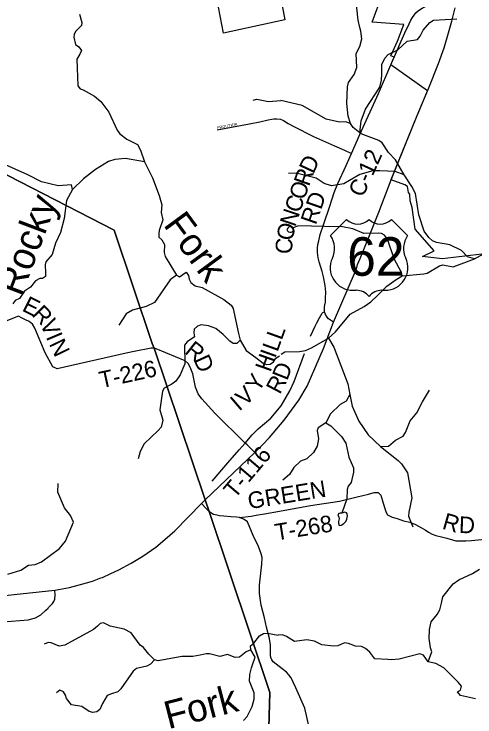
# Model space of a CAD drawing. Extents: x 1525783 to 1900577, y 218250 to 627376.
# Drawn here: x 1644767 to 1653092, y 423185 to 435875 of the extents above; entities that cross this region are included whole.
import ezdxf

# ---------------------------------------------------------------- set-up
doc = ezdxf.new("R2010")
doc.units = 0
for name, color, linetype in [('GM_X_City_Street', 7, 'Continuous'), ('GM_X_Corporation', 7, 'Continuous'), ('GM_X_County_Road', 7, 'Continuous'), ('GM_X_County_Road_Text', 7, 'Continuous'), ('GM_X_Major_River', 7, 'Continuous'), ('GM_X_Minor_Lake', 7, 'Continuous'), ('GM_X_Minor_River', 7, 'Continuous'), ('GM_X_Minor_River_Text', 7, 'Continuous'), ('GM_X_Township', 7, 'Continuous'), ('GM_X_Township_Road', 7, 'Continuous'), ('GM_X_Township_Road_Text', 7, 'Continuous'), ('GM_X_Township_Subdivision', 7, 'Continuous'), ('GM_X_Township_Subdivision_Text', 7, 'Continuous'), ('GM_X_US_Location', 7, 'Continuous'), ('GM_X_US_Route', 7, 'Continuous'), ('GM_X_US_Shield', 7, 'Continuous')]:
    doc.layers.add(name, color=color, linetype=linetype)

msp = doc.modelspace()

# ---------------------------------------------------------------- linework, layer by layer
at = {"layer": 'GM_X_City_Street'}
msp.add_lwpolyline([(1651636, 435106), (1651752, 435375), (1651827, 435534), (1651901, 435696), (1651934, 435763), (1651964, 435814), (1652022, 435895), (1652073, 435938), (1652138, 435980), (1652233, 436027), (1652492, 436161)], dxfattribs=at)
at = {"layer": 'GM_X_Corporation'}
for points in [[(1649445, 436900), (1649655, 435772), (1648549, 435531), (1648159, 437572)], [(1653623, 431587), (1652498, 431458), (1652147, 431497), (1652353, 431602), (1652009, 431989), (1651959, 432381), (1651920, 432500), (1651918, 432624), (1651892, 432652), (1651872, 432760), (1651823, 432794), (1651578, 432880), (1652048, 434046), (1652194, 434384), (1652235, 434487), (1651571, 434961), (1651631, 435095), (1651573, 435119), (1651691, 435387), (1651808, 435686), (1651236, 435730), (1651422, 436242)]]:
    msp.add_lwpolyline(points, dxfattribs=at)
at = {"layer": 'GM_X_County_Road'}
for points in [[(1651572, 434961), (1651603, 435030), (1651636, 435106)], [(1650389, 430658), (1650390, 430666), (1650393, 430707), (1650395, 430745), (1650401, 430857), (1650388, 430975), (1650358, 431130), (1650332, 431225), (1650278, 431400), (1650258, 431475), (1650249, 431570), (1650250, 431646), (1650256, 431715), (1650270, 431781), (1650295, 431895), (1650362, 432088), (1650469, 432405), (1650498, 432502), (1650511, 432542), (1650550, 432653), (1650612, 432816), (1650763, 433142), (1650861, 433359), (1651011, 433703), (1651347, 434438), (1651571, 434961), (1651572, 434961)], [(1650538, 430311), (1650466, 430360), (1650449, 430375), (1650424, 430403), (1650395, 430453), (1650372, 430502), (1650374, 430555), (1650377, 430590), (1650389, 430658)], [(1648295, 426890), (1648290, 426895), (1648236, 426951), (1648155, 427038)], [(1648432, 426828), (1648370, 426842), (1648320, 426869), (1648295, 426890)], [(1650102, 422968), (1650016, 423345), (1649854, 423713), (1649771, 423891), (1649730, 423945), (1649686, 423992), (1649609, 424051), (1649448, 424179), (1649420, 424214), (1649402, 424256), (1649399, 424300), (1649401, 424437), (1649397, 424482), (1649379, 424604), (1649328, 424808), (1649288, 424972), (1649233, 425203), (1649198, 425413), (1649202, 425567), (1649244, 425946), (1649246, 426061), (1649233, 426129), (1649181, 426263), (1649087, 426463), (1648982, 426706), (1648958, 426726), (1648909, 426754), (1648836, 426783), (1648782, 426793), (1648684, 426801), (1648558, 426811), (1648476, 426818), (1648432, 426828)]]:
    msp.add_lwpolyline(points, dxfattribs=at)
at = {"layer": 'GM_X_Major_River'}
msp.add_lwpolyline([(1649593, 429737), (1649659, 429774), (1649920, 429782), (1650030, 429802), (1650141, 429848), (1650445, 430025), (1650571, 430138), (1650837, 430458), (1651090, 430594), (1651211, 430680), (1651331, 430792), (1651497, 430960), (1651667, 431085), (1651778, 431146), (1652169, 431185), (1652226, 431198), (1652454, 431331), (1652513, 431346), (1652700, 431314), (1653083, 431456), (1653356, 431606)], dxfattribs=at)
at = {"layer": 'GM_X_Minor_Lake'}
for points in [[(1649800, 432016), (1649788, 432030), (1649766, 432040), (1649738, 432035), (1649710, 432011), (1649691, 431985), (1649703, 431959), (1649725, 431945), (1649748, 431936), (1649772, 431936), (1649795, 431946), (1649815, 431967), (1649817, 431987)], [(1649817, 431987), (1649800, 432016)], [(1650656, 426863), (1650630, 426859), (1650617, 426833), (1650635, 426791), (1650636, 426759), (1650629, 426715), (1650627, 426683), (1650638, 426643), (1650678, 426650), (1650723, 426675), (1650761, 426715), (1650780, 426758), (1650791, 426814), (1650786, 426855), (1650772, 426871), (1650742, 426885)], [(1650742, 426885), (1650705, 426873), (1650687, 426867), (1650656, 426863)]]:
    msp.add_lwpolyline(points, dxfattribs=at)
at = {"layer": 'GM_X_Minor_River'}
for points in [[(1653083, 431456), (1652956, 431489), (1652846, 431607), (1652637, 431709), (1652400, 431749), (1652326, 431780), (1652257, 431839), (1652177, 431957), (1652076, 432252), (1652017, 432636), (1651951, 432763), (1651813, 432970), (1651654, 433245), (1651532, 433378), (1651413, 433548), (1651354, 433591), (1651065, 433702), (1651012, 433729), (1650893, 433828), (1650843, 433899), (1650801, 434030), (1650777, 434263), (1650788, 434559), (1650810, 434639), (1650910, 434782), (1650961, 434913), (1650945, 435160), (1651010, 435291), (1651050, 435429), (1651031, 435568), (1651012, 435634), (1650980, 435763), (1650934, 436217)], [(1645951, 435876), (1645991, 435720), (1645984, 435668), (1645879, 435561), (1645852, 435507), (1645847, 435457), (1645874, 435327), (1645935, 435282), (1645984, 435217), (1645957, 435148), (1645898, 435062), (1645918, 434582), (1645961, 434525), (1646015, 434504), (1646218, 434395), (1646332, 434294), (1646480, 434106), (1646629, 433781), (1646676, 433715), (1646803, 433619), (1646997, 433520), (1647052, 433416), (1647123, 433210), (1647266, 432920), (1647387, 432602), (1647435, 432430), (1647423, 432292), (1647454, 432159), (1647385, 431970), (1647381, 431916), (1647382, 431846), (1647437, 431797), (1647484, 431712), (1647478, 431570), (1647499, 431496), (1647699, 431161), (1647754, 431130), (1647875, 431214), (1647918, 431156), (1647927, 431088), (1647961, 431031), (1648036, 430970), (1648163, 430936), (1648554, 430721), (1648686, 430619), (1648722, 430557), (1648739, 430502), (1648818, 430105), (1648850, 429986), (1648962, 429801), (1649136, 429674), (1649264, 429572), (1649328, 429551), (1649392, 429557), (1649450, 429598), (1649495, 429661), (1649562, 429705)], [(1651012, 433729), (1651034, 433946), (1651117, 434155), (1651371, 434557), (1651403, 434679), (1651409, 434795), (1651412, 434962), (1651466, 435077), (1651522, 435146), (1651699, 435228), (1651870, 435383), (1652055, 435418), (1652104, 435473), (1652156, 435585), (1652275, 435725), (1652341, 435762), (1652766, 435789)], [(1649087, 434322), (1649151, 434337), (1649364, 434298), (1649588, 434315)], [(1650843, 433899), (1650751, 433930), (1650647, 433922), (1650404, 433976), (1649970, 434222), (1649588, 434315)], [(1647123, 433210), (1646778, 433265), (1646589, 433249), (1646470, 433215), (1646237, 433070), (1646019, 432901), (1645821, 432707), (1645712, 432512), (1645674, 432182), (1645605, 431933), (1645513, 431740), (1645452, 431532), (1645343, 431400), (1645330, 431348), (1645336, 431202), (1645335, 431136), (1645283, 431100), (1645231, 431099), (1645156, 431060), (1645063, 430943), (1644956, 430870), (1644865, 430737), (1644788, 430702), (1644744, 430643)], [(1645821, 432707), (1645802, 432791), (1645566, 432776), (1645261, 432846), (1645017, 432970), (1644558, 433174)], [(1651813, 432970), (1651648, 433033), (1651374, 433046), (1651248, 433042), (1651014, 432977), (1650828, 432872), (1650723, 432812), (1650498, 432776), (1650371, 432816), (1650226, 432911), (1649864, 433005), (1649725, 432997)], [(1651778, 431146), (1651765, 431212), (1651630, 431457), (1651510, 431808), (1651459, 431883), (1651406, 431914), (1651350, 431917), (1651087, 431915), (1650885, 431995), (1650697, 432036), (1650375, 432040), (1649905, 432052), (1649800, 432016)], [(1647699, 431161), (1647584, 431076), (1647303, 430665), (1647152, 430595), (1646906, 430532), (1646791, 430460), (1646658, 430261)], [(1648850, 429986), (1648789, 429927), (1648726, 429928), (1648662, 429967), (1648546, 430092), (1648413, 430198), (1648276, 430248), (1648149, 430262), (1648082, 430243), (1648020, 430189), (1648015, 430119), (1648026, 430049), (1647893, 429957), (1647844, 429897), (1647854, 429559), (1647768, 429364), (1647688, 429245), (1647616, 429191), (1647479, 429123), (1647446, 429065), (1647400, 428728), (1647453, 428541), (1647422, 428419), (1647369, 428356), (1647118, 428117), (1647045, 427975), (1647011, 427846)], [(1650445, 430025), (1650540, 429861), (1650796, 429199), (1650831, 429004), (1650875, 428797), (1650996, 428528), (1651164, 428278), (1651388, 428066), (1651706, 427814), (1651765, 427757), (1651872, 427590), (1651954, 427140), (1651896, 426884), (1651892, 426812), (1651969, 426618)], [(1651388, 428066), (1651533, 428071), (1651659, 428184), (1651794, 428255), (1651840, 428323), (1651921, 428534), (1652040, 428676), (1652144, 428875), (1652268, 429082)], [(1650831, 429004), (1650765, 428889), (1650659, 428824), (1650484, 428657), (1650397, 428494), (1650261, 428406), (1650240, 428354), (1650266, 428207), (1650243, 428071), (1650173, 427958), (1650055, 427848), (1649940, 427800), (1649818, 427687), (1649744, 427560), (1649620, 427462)], [(1650397, 428494), (1650488, 428440), (1650681, 428248), (1650759, 428127), (1650814, 427877), (1650899, 427681), (1650900, 427607), (1650858, 427417), (1650803, 427354), (1650784, 427294), (1650779, 427120), (1650687, 426867)], [(1644657, 425762), (1644892, 425833), (1645029, 425923), (1645085, 425930), (1645147, 425940), (1645265, 425988), (1645590, 426224), (1645693, 426357), (1645842, 426700), (1645785, 426824), (1645677, 426962), (1645555, 427246), (1645561, 427400)], [(1652247, 424180), (1652312, 424362), (1652288, 424432), (1652265, 424601), (1652268, 424761), (1652302, 424905), (1652409, 425032), (1652458, 425119), (1652486, 425241), (1652509, 425353), (1652701, 425588), (1652802, 425661), (1653049, 425777), (1653172, 425855)], [(1649044, 424397), (1648962, 424362), (1648837, 424265), (1648763, 424256), (1648621, 424314), (1648485, 424276), (1648296, 424324), (1648234, 424325), (1648126, 424298), (1647998, 424274), (1647798, 424279), (1647369, 424196), (1647304, 424215), (1647199, 424321), (1647107, 424436), (1647046, 424483), (1646883, 424701), (1646754, 424769), (1646503, 424826), (1646380, 424882), (1646324, 424875), (1646273, 424823), (1646202, 424762), (1645683, 424483), (1645581, 424466), (1645436, 424522), (1645384, 424527), (1645312, 424500)], [(1648912, 423121), (1648977, 423194), (1649067, 423371), (1649102, 423509), (1649102, 423623), (1649019, 423832), (1649026, 423954), (1649058, 424070), (1649076, 424126), (1649120, 424267), (1649044, 424397), (1649035, 424471), (1649097, 424516), (1649201, 424649), (1649272, 424692), (1649345, 424697), (1649539, 424662)], [(1653100, 423514), (1652831, 423572), (1652778, 423636), (1652830, 423671), (1652848, 423739), (1652791, 423814), (1652527, 424071), (1652387, 424152), (1652247, 424180), (1652163, 424300), (1652099, 424323), (1651721, 424227), (1651587, 424215), (1651517, 424221), (1651285, 424237), (1651191, 424355), (1651116, 424422), (1651043, 424455), (1650935, 424465), (1650806, 424512), (1650734, 424521), (1650679, 424500), (1650613, 424471), (1650538, 424462), (1650325, 424490), (1650192, 424556), (1650054, 424575), (1649831, 424546), (1649689, 424635), (1649613, 424670), (1649539, 424662)], [(1647304, 424215), (1647229, 424136), (1647162, 424099), (1646980, 424059), (1646916, 424010), (1646696, 423692), (1646639, 423637), (1646525, 423602), (1646449, 423573), (1646363, 423428), (1646319, 423317), (1646261, 423275), (1646187, 423266), (1646123, 423285), (1645991, 423373), (1645805, 423402), (1645715, 423517), (1645698, 423577), (1645660, 423640), (1645593, 423669), (1645532, 423623)]]:
    msp.add_lwpolyline(points, dxfattribs=at)
at = {"layer": 'GM_X_Township'}
for points in [[(1681025, 444291), (1679871, 434929), (1679454, 431544), (1678924, 427242), (1677405, 426800), (1673144, 425561), (1668810, 424300), (1663005, 422598), (1662544, 422468), (1661917, 422302), (1655652, 418075), (1649010, 418793), (1649278, 420121), (1649290, 420273), (1649389, 423628), (1648290, 426895), (1648220, 427103), (1647298, 429844), (1647262, 429928), (1646572, 431971), (1642730, 433950)], [(1642730, 433950), (1646572, 431971), (1647262, 429928), (1647298, 429844), (1648220, 427103), (1648290, 426895), (1649389, 423628), (1649290, 420273), (1649278, 420121), (1649010, 418793), (1648706, 417404), (1647880, 413222)]]:
    msp.add_lwpolyline(points, dxfattribs=at)
at = {"layer": 'GM_X_Township_Road'}
for points in [[(1650120, 430062), (1650204, 430241), (1650238, 430301), (1650286, 430391), (1650331, 430473), (1650345, 430489), (1650372, 430502)], [(1646790, 429751), (1645543, 429470), (1645468, 429508), (1645331, 429759), (1645140, 430205), (1645100, 430275), (1645039, 430324), (1644973, 430354), (1644914, 430386), (1644845, 430418), (1644383, 430239)], [(1648975, 428096), (1648940, 428130), (1648393, 428672), (1648161, 428926), (1648094, 429019), (1648045, 429137), (1647996, 429379), (1647946, 429500), (1647911, 429564), (1647857, 429616), (1647336, 429834), (1647298, 429844), (1647242, 429845), (1646938, 429784), (1646790, 429751)], [(1648348, 427441), (1648625, 427773), (1648832, 428009), (1648940, 428130), (1649068, 428277), (1649173, 428384), (1649402, 428580), (1649589, 428799), (1649748, 429075), (1649828, 429242), (1650010, 429747)], [(1649115, 427961), (1648975, 428096)], [(1648836, 426783), (1649048, 426808), (1649142, 426830), (1649291, 426851), (1649560, 426902), (1650119, 427001), (1650644, 427082), (1650967, 427158), (1651168, 427209), (1651272, 427235), (1651342, 427237), (1651390, 427191), (1651436, 427042), (1651469, 426930), (1651487, 426876), (1651511, 426832), (1651595, 426795), (1651687, 426769), (1651751, 426743), (1651799, 426727), (1651915, 426704), (1652017, 426658), (1652129, 426598), (1652195, 426562), (1652255, 426523), (1652319, 426485), (1652387, 426461), (1652485, 426439), (1652586, 426410), (1652686, 426382), (1652746, 426366), (1652926, 426364), (1653030, 426373), (1653273, 426397)], [(1645383, 425152), (1645391, 425160), (1645462, 425234), (1645486, 425270), (1645503, 425314), (1645508, 425391), (1645503, 425474)], [(1643907, 425159), (1644083, 425026), (1644236, 424944), (1644395, 424909), (1644571, 424905), (1645024, 424938), (1645154, 424973), (1645250, 425028), (1645343, 425110), (1645383, 425152)]]:
    msp.add_lwpolyline(points, dxfattribs=at)
at = {"layer": 'GM_X_Township_Subdivision'}
msp.add_lwpolyline([(1648438, 433784), (1649021, 433891), (1649203, 433930), (1649357, 433967), (1649420, 433978), (1649461, 433986), (1649513, 433986), (1649581, 433976), (1649635, 433951), (1649715, 433902), (1649823, 433844), (1650175, 433666), (1650555, 433495), (1650734, 433419), (1650861, 433359)], dxfattribs=at)
at = {"layer": 'GM_X_US_Route'}
for points in [[(1652258, 434543), (1652432, 434981), (1652535, 435263), (1652613, 435535), (1652671, 435747), (1652735, 435990)], [(1652054, 434058), (1652194, 434384), (1652258, 434543)], [(1651581, 432888), (1652048, 434046), (1652054, 434058)], [(1650422, 430010), (1650538, 430311), (1650934, 431235), (1650961, 431299), (1650971, 431353), (1651016, 431463), (1651209, 431939), (1651356, 432297), (1651578, 432880), (1651581, 432888)], [(1649253, 428098), (1649383, 428228), (1649647, 428544), (1649910, 428903), (1650062, 429158), (1650355, 429838), (1650422, 430010)], [(1646335, 425694), (1646365, 425705), (1646512, 425773), (1646660, 425843), (1646884, 425964), (1647092, 426085), (1647325, 426253), (1647489, 426386), (1647669, 426548), (1648155, 427038), (1648220, 427103), (1649115, 427961), (1649185, 428029), (1649253, 428098)], [(1640793, 423231), (1641549, 424042), (1641888, 424416), (1642101, 424640), (1642269, 424800), (1642396, 424895), (1642540, 424992), (1642685, 425067), (1642874, 425142), (1642996, 425178), (1643094, 425203), (1643201, 425221), (1643683, 425274), (1644766, 425393), (1645503, 425474), (1645766, 425521), (1645969, 425576), (1646183, 425637), (1646335, 425694)]]:
    msp.add_lwpolyline(points, dxfattribs=at)
at = {"layer": 'GM_X_US_Shield'}
for p, q in [((1650772, 432165), (1650482, 431875)), ((1651874, 431875), (1651584, 432165)), ((1650888, 430889), (1650946, 430889)), ((1651410, 430889), (1651468, 430889))]:
    msp.add_line(p, q, dxfattribs=at)
for centre, radius, start, end in [((1650975, 432373), 290, 225.573, 314.427), ((1651381, 432373), 290, 225.573, 314.427), ((1650149, 431642), 406, 334.5471, 35.0009), ((1652207, 431642), 406, 144.9991, 205.4529), ((1650883, 431295), 406, 154.8319, 270.6383), ((1651473, 431295), 406, 269.3617, 25.1681), ((1650946, 430599), 290, 36.8699, 90), ((1651410, 430599), 290, 90, 143.1301)]:
    msp.add_arc(centre, radius, start, end, dxfattribs=at)

# ---------------------------------------------------------------- texts
at = {"layer": 'GM_X_County_Road_Text'}
for s, rotation, p in [('C-12', 65.5818, (1651067, 432550)), ('D', 64.8849, (1650173, 432976)), ('R', 70.422, (1650093, 432751)), ('O', 71.0091, (1650007, 432502)), ('C', 71.0096, (1649927, 432269)), ('RD', 70.78, (1650217, 432056)), ('N', 71.4861, (1649844, 432020)), ('O', 79.4105, (1649798, 431771)), ('C', 86.4224, (1649784, 431535))]:
    msp.add_text(s, height=300, rotation=rotation, dxfattribs=at).set_placement(p)
at = {"layer": 'GM_X_Minor_River_Text'}
for s, height, rotation, p in [('Rocky', 499.9, 69.302, (1644899, 430759)), ('Fork', 500, 306.3017, (1647451, 432069)), ('Fork', 500, 14.4747, (1647553, 422962))]:
    msp.add_text(s, height=height, rotation=rotation, dxfattribs=at).set_placement(p)
at = {"layer": 'GM_X_Township_Road_Text'}
for s, rotation, p in [('E', 333.6065, (1644895, 430525)), ('R', 314.3252, (1645074, 430441)), ('V', 293.713, (1645230, 430288)), ('L', 70.3279, (1649601, 429974)), ('I', 292.9039, (1645336, 430048)), ('N', 295.8549, (1645391, 429919)), ('R', 321.7273, (1647832, 429760)), ('L', 70.3279, (1649525, 429763)), ('I', 70.3283, (1649484, 429647)), ('D', 294.5511, (1648003, 429637)), ('H', 70.6296, (1649396, 429398)), ('T-226', 12.3824, (1646341, 429117)), ('D', 68.5771, (1649698, 429245)), ('Y', 58.2256, (1649183, 429030)), ('R', 62.3404, (1649569, 428995)), ('V', 43.2905, (1648938, 428784)), ('I', 40.6216, (1648833, 428694)), ('T-116', 49.6979, (1648754, 427111)), ('GREEN', 9.2593, (1649013, 426935)), ('T-268', 9.2701, (1649504, 426369)), ('R', 343.9812, (1652484, 426587)), ('D', 357.9692, (1652798, 426507))]:
    msp.add_text(s, height=300, rotation=rotation, dxfattribs=at).set_placement(p)
at = {"layer": 'GM_X_Township_Subdivision_Text'}
for s, rotation, p in [('PROUTY', 10.3034, (1648439, 433797)), ('DR', 12.5224, (1648708, 433845))]:
    msp.add_text(s, height=50, rotation=rotation, dxfattribs=at).set_placement(p)
at = {"layer": 'GM_X_US_Location'}
for s in ['0', '/']:
    msp.add_text(s, height=1, dxfattribs=at).set_placement((1651178, 431493))
msp.add_text('62', height=1, rotation=0, dxfattribs=at).set_placement((1650971, 431286))
at = {"layer": 'GM_X_US_Shield'}
msp.add_text('62', height=696.1, dxfattribs=at).set_placement((1650784, 431150))

doc.saveas('drawing.dxf')
